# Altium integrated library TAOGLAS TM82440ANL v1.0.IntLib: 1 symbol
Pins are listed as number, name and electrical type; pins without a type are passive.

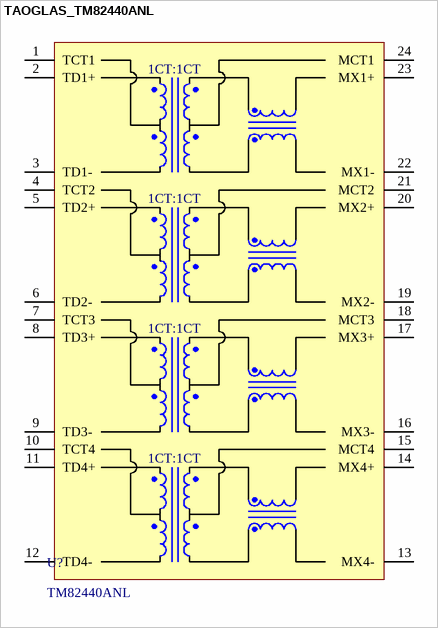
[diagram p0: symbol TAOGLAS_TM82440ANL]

## TAOGLAS_TM82440ANL
designator U?, comment TM82440ANL
1000 Base-T/1G transformer Single Port and 24pin SMT; ComponentLibStatus: Created; MFG: Taoglas; Temp_High: +85C; Temp_Low: -40C
footprint TAOGLAS_TM82440ANL (1000 Base-T/1G transformer Single Port and 24pin SMT)
pins: 1 TCT1, 2 TD1+, 3 TD1-, 4 TCT2, 5 TD2+, 6 TD2-, 7 TCT3, 8 TD3+, 9 TD3-, 10 TCT4, 11 TD4+, 12 TD4-, 13 MX4-, 14 MX4+, 15 MCT4, 16 MX3-, 17 MX3+, 18 MCT3, 19 MX2-, 20 MX2+, 21 MCT2, 22 MX1-, 23 MX1+, 24 MCT1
